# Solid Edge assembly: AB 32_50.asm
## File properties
Title: Zylinder
Author: ahadarics
Template: iso metric assembly.asm
Last saved by: ahadarics
Revision: 7
Application: Solid Edge
Username: ahadarics
Dokumentum tartalom típus: 1
Document Number: AB 32/50
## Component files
Profilrohr.par
Kolbenstange.par
Kit_1.par
Kit_2.par
Mutter_1.par
Mutter_2.par
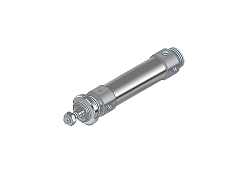
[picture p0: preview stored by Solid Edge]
